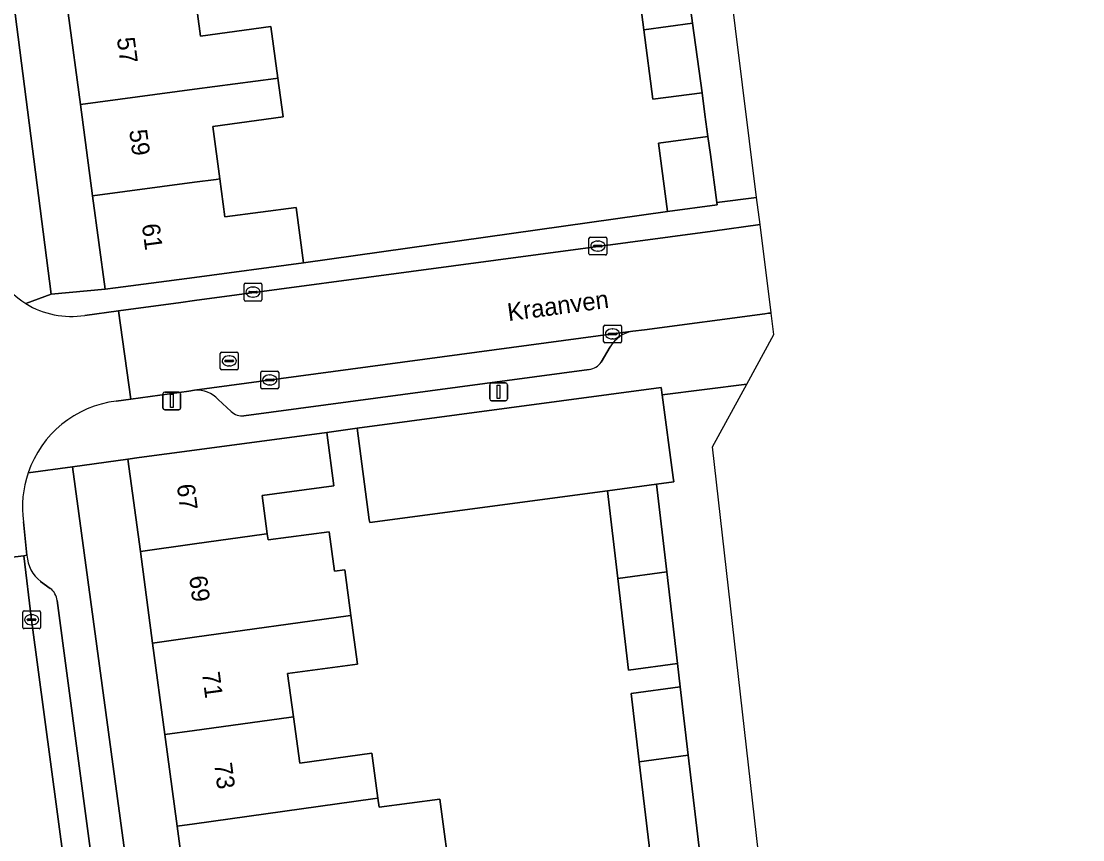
# Model space of a CAD drawing. Extents: x 163147 to 163550, y 380933 to 381639.
# Drawn here: x 163490.3 to 163549.9, y 381293.5 to 381339.4 of the extents above; entities that cross this region are included whole.
import ezdxf

# ---------------------------------------------------------------- set-up
doc = ezdxf.new("R2010")
doc.units = 0
for name, color, linetype in [('IMGEO_Erf', 7, 'Continuous'), ('IMGEO_Kolk', 7, 'Continuous'), ('IMGEO_Lichtmast', 7, 'Continuous'), ('IMGEO_Muur', 7, 'Continuous'), ('IMGEO_Openbare_ruimte_label', 7, 'Continuous'), ('IMGEO_Pand', 7, 'Continuous'), ('IMGEO_Pand_nummerreeks', 7, 'Continuous'), ('IMGEO_Parkeervlak_open', 7, 'Continuous'), ('IMGEO_Rijbaan_lokaal_open', 7, 'Continuous'), ('IMGEO_Rioolput', 7, 'Continuous'), ('IMGEO_Voetpad_open', 7, 'Continuous')]:
    doc.layers.add(name, color=color, linetype=linetype)

msp = doc.modelspace()

# ---------------------------------------------------------------- linework, layer by layer
at = {"layer": 'IMGEO_Erf'}
for points in [[(163487.783, 381356.32), (163491.94, 381324.111), (163494.978, 381324.392), (163494.274, 381329.637), (163493.586, 381334.763), (163492.898, 381339.89)], [(163500.033, 381340.835), (163500.331, 381338.604), (163504.288, 381339.132), (163504.676, 381336.232), (163504.966, 381334.06), (163501.026, 381333.533), (163501.42, 381330.584), (163501.705, 381328.452), (163505.703, 381328.986), (163506.119, 381325.868), (163526.558, 381328.752), (163526.055, 381332.589), (163528.823, 381332.956), (163528.656, 381334.194), (163528.491, 381335.418), (163525.733, 381335.053), (163525.222, 381338.955), (163524.714, 381342.835)], [(163525.611, 381292.402), (163524.968, 381297.87), (163524.517, 381301.709), (163527.27, 381302.09), (163527.116, 381303.397), (163524.363, 381303.016), (163523.757, 381308.165), (163523.178, 381313.092), (163509.829, 381311.3), (163509.807, 381311.462), (163509.122, 381316.592), (163507.426, 381316.365), (163507.826, 381313.367), (163503.792, 381312.828), (163504.081, 381310.668), (163504.126, 381310.33), (163507.551, 381310.789), (163507.848, 381308.578), (163508.435, 381308.656), (163508.778, 381306.087), (163509.142, 381303.362), (163505.221, 381302.826), (163505.549, 381300.408), (163505.901, 381297.81), (163509.948, 381298.359), (163510.29, 381295.834), (163510.358, 381295.333), (163513.772, 381295.791), (163514.431, 381290.881)]]:
    msp.add_lwpolyline(points, dxfattribs=at)
msp.add_lwpolyline([(163497.642, 381304.544), (163496.953, 381309.68), (163496.257, 381314.866), (163493.134, 381314.437), (163496.679, 381288.37), (163499.757, 381288.789), (163499.021, 381294.272), (163498.332, 381299.408)], close=True, dxfattribs=at)
at = {"layer": 'IMGEO_Kolk'}
for p, q in [((163522.141, 381326.39), (163522.141, 381327.242)), ((163522.216, 381327.316), (163523.068, 381327.316)), ((163523.142, 381327.242), (163523.142, 381326.39)), ((163522.4, 381326.81), (163522.4, 381326.822)), ((163522.838, 381326.773), (163522.44, 381326.773)), ((163522.443, 381326.859), (163522.841, 381326.859)), ((163522.629, 381327.096), (163522.654, 381327.096)), ((163522.884, 381326.822), (163522.884, 381326.81)), ((163523.068, 381326.316), (163522.216, 381326.316)), ((163522.652, 381326.536), (163522.627, 381326.536)), ((163502.776, 381323.807), (163502.776, 381324.659)), ((163502.851, 381324.733), (163503.703, 381324.733)), ((163503.035, 381324.227), (163503.035, 381324.239)), ((163503.473, 381324.19), (163503.075, 381324.19)), ((163503.078, 381324.276), (163503.476, 381324.276)), ((163503.264, 381324.513), (163503.289, 381324.513)), ((163503.519, 381324.239), (163503.519, 381324.227)), ((163503.777, 381324.659), (163503.777, 381323.807)), ((163503.703, 381323.733), (163502.851, 381323.733)), ((163503.287, 381323.953), (163503.262, 381323.953)), ((163522.964, 381321.459), (163522.964, 381322.311)), ((163523.039, 381322.385), (163523.891, 381322.385)), ((163523.223, 381321.879), (163523.223, 381321.891)), ((163523.661, 381321.842), (163523.263, 381321.842)), ((163523.266, 381321.928), (163523.664, 381321.928)), ((163523.452, 381322.165), (163523.477, 381322.165)), ((163523.707, 381321.891), (163523.707, 381321.879)), ((163523.965, 381322.311), (163523.965, 381321.459)), ((163523.891, 381321.385), (163523.039, 381321.385)), ((163523.475, 381321.605), (163523.45, 381321.605)), ((163503.72, 381318.877), (163503.72, 381319.729)), ((163503.795, 381319.803), (163504.647, 381319.803)), ((163504.208, 381319.583), (163504.233, 381319.583)), ((163504.721, 381319.729), (163504.721, 381318.877)), ((163503.979, 381319.297), (163503.979, 381319.309)), ((163504.417, 381319.26), (163504.019, 381319.26)), ((163504.022, 381319.346), (163504.42, 381319.346)), ((163504.231, 381319.023), (163504.206, 381319.023)), ((163504.463, 381319.309), (163504.463, 381319.297)), ((163504.647, 381318.803), (163503.795, 381318.803)), ((163490.421, 381306.349), (163491.273, 381306.349)), ((163490.346, 381305.423), (163490.346, 381306.275)), ((163490.605, 381305.843), (163490.605, 381305.855)), ((163491.043, 381305.806), (163490.645, 381305.806)), ((163490.648, 381305.892), (163491.046, 381305.892)), ((163490.834, 381306.129), (163490.859, 381306.129)), ((163491.089, 381305.855), (163491.089, 381305.843)), ((163491.347, 381306.275), (163491.347, 381305.423)), ((163491.273, 381305.349), (163490.421, 381305.349)), ((163490.857, 381305.569), (163490.832, 381305.569))]:
    msp.add_line(p, q, dxfattribs=at)
for points in [[(163522.141, 381326.39), (163522.141, 381327.242)], [(163522.216, 381327.316), (163523.068, 381327.316)], [(163523.142, 381327.242), (163523.142, 381326.39)], [(163523.068, 381326.316), (163522.216, 381326.316)], [(163502.776, 381323.807), (163502.776, 381324.659)], [(163502.851, 381324.733), (163503.703, 381324.733)], [(163503.777, 381324.659), (163503.777, 381323.807)], [(163503.703, 381323.733), (163502.851, 381323.733)], [(163522.964, 381321.459), (163522.964, 381322.311)], [(163523.039, 381322.385), (163523.891, 381322.385)], [(163523.965, 381322.311), (163523.965, 381321.459)], [(163523.891, 381321.385), (163523.039, 381321.385)], [(163503.72, 381318.877), (163503.72, 381319.729)], [(163503.795, 381319.803), (163504.647, 381319.803)], [(163504.721, 381319.729), (163504.721, 381318.877)], [(163504.647, 381318.803), (163503.795, 381318.803)], [(163490.421, 381306.349), (163491.273, 381306.349)], [(163490.346, 381305.423), (163490.346, 381306.275)], [(163491.347, 381306.275), (163491.347, 381305.423)], [(163491.273, 381305.349), (163490.421, 381305.349)]]:
    msp.add_lwpolyline(points, dxfattribs=at)
for centre, radius, start, end in [((163522.218, 381327.24), 0.0765, 91.55205, 178.44795), ((163522.218, 381327.24), 0.0765, 91.55205, 178.44795), ((163523.066, 381327.24), 0.0765, 1.55205, 88.44795), ((163523.066, 381327.24), 0.0765, 1.55205, 88.44795), ((163522.44, 381326.819), 0.0403, 85.87752, 175.75265), ((163522.437, 381326.809), 0.0366, 178.93798, 274.71019), ((163522.841, 381326.816), 0.043, 264.86636, 352.45326), ((163522.845, 381326.821), 0.0386, 1.73085, 96.63898), ((163522.218, 381326.392), 0.0765, 181.55205, 268.44795), ((163522.218, 381326.392), 0.0765, 181.55205, 268.44795), ((163523.066, 381326.392), 0.0765, 271.55205, 358.44795), ((163523.066, 381326.392), 0.0765, 271.55205, 358.44795), ((163502.853, 381324.657), 0.0765, 91.55205, 178.44795), ((163502.853, 381324.657), 0.0765, 91.55205, 178.44795), ((163503.075, 381324.236), 0.0403, 85.87752, 175.75265), ((163503.072, 381324.226), 0.0366, 178.93798, 274.71019), ((163503.476, 381324.233), 0.043, 264.86636, 352.45326), ((163503.48, 381324.238), 0.0386, 1.73085, 96.63898), ((163503.701, 381324.657), 0.0765, 1.55205, 88.44795), ((163503.701, 381324.657), 0.0765, 1.55205, 88.44795), ((163502.853, 381323.809), 0.0765, 181.55205, 268.44795), ((163502.853, 381323.809), 0.0765, 181.55205, 268.44795), ((163503.701, 381323.809), 0.0765, 271.55205, 358.44795), ((163503.701, 381323.809), 0.0765, 271.55205, 358.44795), ((163523.041, 381322.309), 0.0765, 91.55205, 178.44795), ((163523.041, 381322.309), 0.0765, 91.55205, 178.44795), ((163523.263, 381321.888), 0.0403, 85.87752, 175.75265), ((163523.26, 381321.878), 0.0366, 178.93798, 274.71019), ((163523.664, 381321.885), 0.043, 264.86636, 352.45326), ((163523.668, 381321.89), 0.0386, 1.73085, 96.63898), ((163523.889, 381322.309), 0.0765, 1.55205, 88.44795), ((163523.889, 381322.309), 0.0765, 1.55205, 88.44795), ((163523.041, 381321.461), 0.0765, 181.55205, 268.44795), ((163523.041, 381321.461), 0.0765, 181.55205, 268.44795), ((163523.889, 381321.461), 0.0765, 271.55205, 358.44795), ((163523.889, 381321.461), 0.0765, 271.55205, 358.44795), ((163503.797, 381319.727), 0.0765, 91.55205, 178.44795), ((163503.797, 381319.727), 0.0765, 91.55205, 178.44795), ((163504.645, 381319.727), 0.0765, 1.55205, 88.44795), ((163504.645, 381319.727), 0.0765, 1.55205, 88.44795), ((163503.797, 381318.879), 0.0765, 181.55205, 268.44795), ((163503.797, 381318.879), 0.0765, 181.55205, 268.44795), ((163504.019, 381319.306), 0.0403, 85.87752, 175.75265), ((163504.016, 381319.296), 0.0366, 178.93798, 274.71019), ((163504.42, 381319.303), 0.043, 264.86636, 352.45326), ((163504.424, 381319.308), 0.0386, 1.73085, 96.63898), ((163504.645, 381318.879), 0.0765, 271.55205, 358.44795), ((163504.645, 381318.879), 0.0765, 271.55205, 358.44795), ((163490.423, 381306.273), 0.0765, 91.55205, 178.44795), ((163490.423, 381306.273), 0.0765, 91.55205, 178.44795), ((163491.271, 381306.273), 0.0765, 1.55205, 88.44795), ((163491.271, 381306.273), 0.0765, 1.55205, 88.44795), ((163490.645, 381305.852), 0.0403, 85.87752, 175.75265), ((163490.642, 381305.842), 0.0366, 178.93798, 274.71019), ((163491.046, 381305.849), 0.043, 264.86636, 352.45326), ((163491.05, 381305.854), 0.0386, 1.73085, 96.63898), ((163490.423, 381305.425), 0.0765, 181.55205, 268.44795), ((163490.423, 381305.425), 0.0765, 181.55205, 268.44795), ((163491.271, 381305.425), 0.0765, 271.55205, 358.44795), ((163491.271, 381305.425), 0.0765, 271.55205, 358.44795)]:
    msp.add_arc(centre, radius, start, end, dxfattribs=at)
for centre, major_axis, ratio, start_param, end_param in [((163522.628, 381326.816), (-0.387, 0.002), 0.722429, 4.712389, 7.853982), ((163522.653, 381326.816), (-0.39, 0.002), 0.717154, 1.570796, 4.712389), ((163503.263, 381324.233), (-0.387, 0.002), 0.722429, 4.712389, 7.853982), ((163503.288, 381324.233), (-0.39, 0.002), 0.717154, 1.570796, 4.712389), ((163523.451, 381321.885), (-0.387, 0.002), 0.722429, 4.712389, 7.853982), ((163523.476, 381321.885), (-0.39, 0.002), 0.717154, 1.570796, 4.712389), ((163504.207, 381319.303), (-0.387, 0.002), 0.722429, 4.712389, 7.853982), ((163504.232, 381319.303), (-0.39, 0.002), 0.717154, 1.570796, 4.712389), ((163490.833, 381305.849), (-0.387, 0.002), 0.722429, 4.712389, 7.853982), ((163490.858, 381305.849), (-0.39, 0.002), 0.717154, 1.570796, 4.712389)]:
    msp.add_ellipse(centre, major_axis=major_axis, ratio=ratio, start_param=start_param, end_param=end_param, dxfattribs=at)
at = {"layer": 'IMGEO_Lichtmast'}
for p, q in [((163516.571, 381318.238), (163516.571, 381319.038)), ((163516.571, 381319.038), (163516.571, 381318.238)), ((163516.671, 381319.138), (163517.461, 381319.138)), ((163517.461, 381319.138), (163516.671, 381319.138)), ((163517.561, 381319.038), (163517.561, 381318.238)), ((163517.561, 381318.238), (163517.561, 381319.038)), ((163498.219, 381317.728), (163498.219, 381318.528)), ((163498.219, 381318.528), (163498.219, 381317.728)), ((163498.319, 381318.628), (163499.109, 381318.628)), ((163499.109, 381318.628), (163498.319, 381318.628)), ((163499.209, 381318.528), (163499.209, 381317.728)), ((163499.209, 381317.728), (163499.209, 381318.528)), ((163517.461, 381318.138), (163516.671, 381318.138)), ((163516.671, 381318.138), (163517.461, 381318.138)), ((163499.109, 381317.628), (163498.319, 381317.628)), ((163498.319, 381317.628), (163499.109, 381317.628))]:
    msp.add_line(p, q, dxfattribs=at)
for points in [[(163516.991, 381319.013), (163517.141, 381319.013), (163517.141, 381318.263), (163516.991, 381318.263), (163516.991, 381319.013)], [(163498.639, 381318.503), (163498.789, 381318.503), (163498.789, 381317.753), (163498.639, 381317.753), (163498.639, 381318.503)]]:
    msp.add_lwpolyline(points, dxfattribs=at)
for centre, start, end in [((163516.671, 381319.038), 90, 180), ((163516.671, 381319.038), 90, 180), ((163517.461, 381319.038), 0, 90), ((163517.461, 381319.038), 360, 90), ((163498.319, 381318.528), 90, 180), ((163498.319, 381318.528), 90, 180), ((163499.109, 381318.528), 0, 90), ((163499.109, 381318.528), 360, 90), ((163516.671, 381318.238), 180, 270), ((163516.671, 381318.238), 180, 270), ((163517.461, 381318.238), 270, 0), ((163517.461, 381318.238), 270, 0), ((163498.319, 381317.728), 180, 270), ((163498.319, 381317.728), 180, 270), ((163499.109, 381317.728), 270, 0), ((163499.109, 381317.728), 270, 0)]:
    msp.add_arc(centre, 0.1, start, end, dxfattribs=at)
at = {"layer": 'IMGEO_Muur'}
msp.add_lwpolyline([(163506.119, 381325.868), (163526.558, 381328.752)], dxfattribs=at)
at = {"layer": 'IMGEO_Pand'}
for points in [[(163527.441, 381343.197), (163524.714, 381342.835), (163525.222, 381338.955), (163527.965, 381339.319)], [(163504.676, 381336.232), (163504.288, 381339.132), (163500.331, 381338.604), (163500.033, 381340.835), (163499.837, 381340.809), (163492.898, 381339.89), (163493.586, 381334.763), (163500, 381335.613), (163504.561, 381336.217)], [(163527.965, 381339.319), (163525.222, 381338.955), (163525.733, 381335.053), (163528.491, 381335.418)], [(163501.42, 381330.584), (163501.026, 381333.533), (163504.966, 381334.06), (163504.676, 381336.232), (163504.561, 381336.217), (163500, 381335.613), (163493.586, 381334.763), (163494.274, 381329.637), (163500, 381330.396), (163501.218, 381330.557)], [(163528.823, 381332.956), (163526.055, 381332.589), (163526.558, 381328.752), (163529.342, 381329.128), (163529.325, 381329.257), (163528.958, 381331.96)], [(163501.42, 381330.584), (163501.218, 381330.557), (163500, 381330.396), (163494.274, 381329.637), (163494.978, 381324.392), (163495.551, 381324.468), (163500, 381325.057), (163506.119, 381325.868), (163505.703, 381328.986), (163501.705, 381328.452)], [(163525.933, 381313.462), (163526.899, 381313.591), (163526.867, 381313.827), (163526.248, 381318.462), (163526.192, 381318.885), (163509.122, 381316.592), (163509.807, 381311.462), (163509.829, 381311.3), (163523.178, 381313.092)], [(163504.081, 381310.668), (163503.792, 381312.828), (163507.826, 381313.367), (163507.426, 381316.365), (163500, 381315.368), (163496.878, 381314.949), (163496.257, 381314.866), (163496.953, 381309.68), (163500, 381310.102), (163503.902, 381310.643)], [(163526.511, 381308.547), (163525.933, 381313.462), (163523.178, 381313.092), (163523.757, 381308.165)], [(163508.435, 381308.656), (163507.848, 381308.578), (163507.551, 381310.789), (163504.126, 381310.33), (163504.081, 381310.668), (163503.902, 381310.643), (163500, 381310.102), (163496.953, 381309.68), (163497.642, 381304.544), (163500, 381304.87), (163508.624, 381306.066), (163508.778, 381306.087)], [(163527.116, 381303.397), (163526.511, 381308.547), (163523.757, 381308.165), (163524.363, 381303.016)], [(163508.778, 381306.087), (163508.624, 381306.066), (163500, 381304.87), (163497.642, 381304.544), (163498.332, 381299.408), (163500, 381299.639), (163505.296, 381300.373), (163505.549, 381300.408), (163505.221, 381302.826), (163509.142, 381303.362)], [(163527.27, 381302.09), (163524.517, 381301.709), (163524.968, 381297.87), (163527.721, 381298.252)], [(163499.021, 381294.272), (163500, 381294.407), (163510.008, 381295.795), (163510.29, 381295.834), (163509.948, 381298.359), (163505.901, 381297.81), (163505.549, 381300.408), (163505.296, 381300.373), (163500, 381299.639), (163498.332, 381299.408)], [(163524.968, 381297.87), (163525.611, 381292.402), (163528.371, 381292.726), (163527.721, 381298.252)], [(163513.772, 381295.791), (163510.358, 381295.333), (163510.29, 381295.834), (163510.008, 381295.795), (163500, 381294.407), (163499.021, 381294.272), (163499.757, 381288.789), (163500, 381288.822), (163504.721, 381289.462), (163506.927, 381289.76), (163506.951, 381289.586), (163511.289, 381290.168), (163511.262, 381290.373), (163511.251, 381290.454), (163514.431, 381290.881)]]:
    msp.add_lwpolyline(points, close=True, dxfattribs=at)
at = {"layer": 'IMGEO_Parkeervlak_open'}
for points in [[(163532.367, 381323.051), (163532.365, 381323.067), (163532.223, 381323.048), (163532.367, 381323.051)], [(163524.612, 381322.04), (163500, 381318.735)], [(163522.828, 381320.305), (163523.34, 381321.154)], [(163502.768, 381317.294), (163522.155, 381319.882)], [(163501.319, 381318.211), (163502.055, 381317.543)], [(163490.584, 381309.465), (163490.402, 381309.443), (163490.846, 381305.849), (163493.759, 381284.035), (163496.541, 381263.222), (163497.43, 381256.373), (163497.739, 381256.415), (163498.362, 381251.625), (163498.069, 381251.55), (163498.277, 381250), (163499.186, 381243.223), (163500, 381237.114), (163502.031, 381221.873), (163503.782, 381208.782)], [(163491.895, 381307.604), (163491.355, 381308.001)], [(163504.96, 381211.766), (163500, 381248.982), (163499.864, 381250), (163492.278, 381306.923)]]:
    msp.add_lwpolyline(points, dxfattribs=at)
for centre, radius, start, end in [((163532.34, 381321.083), 1.968, 89.20328, 89.21682), ((163524.884, 381320.293), 1.768, 98.86148, 150.85609), ((163521.96, 381320.939), 1.075, 280.45491, 323.84619), ((163500.105, 381317.077), 1.662, 43.05366, 93.6134), ((163502.673, 381318.166), 0.878, 225.26376, 276.23492), ((163492.583, 381309.583), 2.002, 183.36688, 232.17923), ((163491.313, 381306.828), 0.97, 5.59617, 53.11135)]:
    msp.add_arc(centre, radius, start, end, dxfattribs=at)
at = {"layer": 'IMGEO_Rijbaan_lokaal_open'}
for points in [[(163527.441, 381343.197), (163527.965, 381339.319), (163528.491, 381335.418), (163528.656, 381334.194), (163528.823, 381332.956), (163528.958, 381331.96), (163529.325, 381329.257), (163531.559, 381329.55), (163510.586, 381498.135)], [(163532.365, 381323.067), (163531.749, 381328.021), (163531.749, 381328.021), (163529.073, 381327.662), (163500, 381323.758), (163499.23, 381323.655), (163495.731, 381323.177), (163496.421, 381318.221), (163499.683, 381318.682), (163500, 381318.735), (163524.612, 381322.04), (163525.264, 381322.126), (163532.015, 381323.02), (163532.223, 381323.048), (163532.365, 381323.067)], [(163495.731, 381323.177), (163493.833, 381322.927)], [(163495.598, 381318.116), (163496.421, 381318.221), (163495.731, 381323.177)], [(163549.87, 381132.002), (163529.08, 381315.546), (163531.005, 381319.076), (163526.248, 381318.462), (163526.867, 381313.827), (163526.899, 381313.591), (163525.933, 381313.462), (163526.511, 381308.547), (163527.116, 381303.397), (163527.27, 381302.09), (163527.721, 381298.252), (163528.371, 381292.726)], [(163486.239, 381310.132), (163486.415, 381308.977), (163486.73, 381309.012), (163490.402, 381309.443), (163490.584, 381309.465), (163490.394, 381311.344)]]:
    msp.add_lwpolyline(points, dxfattribs=at)
msp.add_lwpolyline([(163494.08, 381255.92), (163497.43, 381256.373), (163496.541, 381263.222), (163493.759, 381284.035), (163490.846, 381305.849), (163490.402, 381309.443), (163486.73, 381309.012), (163487.468, 381304.821), (163488.958, 381294.533), (163488.987, 381294.337), (163489.02, 381294.106), (163490.135, 381285.185), (163490.149, 381285.047), (163490.358, 381282.994), (163493.013, 381263.045)], close=True, dxfattribs=at)
for centre, radius, start, end in [((163493.064, 381327.696), 4.828, 185.34699, 238.2884), ((163493.068, 381327.697), 4.831, 238.24928, 279.11087), ((163496.315, 381312.18), 5.979, 96.88985, 161.2586), ((163496.325, 381312.178), 5.989, 161.26652, 187.99994)]:
    msp.add_arc(centre, radius, start, end, dxfattribs=at)
at = {"layer": 'IMGEO_Rioolput'}
for p, q in [((163501.443, 381319.944), (163501.443, 381320.796)), ((163501.518, 381320.87), (163502.37, 381320.87)), ((163501.931, 381320.65), (163501.956, 381320.65)), ((163502.444, 381320.796), (163502.444, 381319.944)), ((163501.702, 381320.364), (163501.702, 381320.376)), ((163502.14, 381320.327), (163501.742, 381320.327)), ((163501.745, 381320.413), (163502.143, 381320.413)), ((163501.954, 381320.09), (163501.929, 381320.09)), ((163502.186, 381320.376), (163502.186, 381320.364)), ((163502.37, 381319.87), (163501.518, 381319.87))]:
    msp.add_line(p, q, dxfattribs=at)
for points in [[(163501.443, 381319.944), (163501.443, 381320.796)], [(163501.518, 381320.87), (163502.37, 381320.87)], [(163502.444, 381320.796), (163502.444, 381319.944)], [(163502.37, 381319.87), (163501.518, 381319.87)]]:
    msp.add_lwpolyline(points, dxfattribs=at)
for centre, radius, start, end in [((163501.52, 381320.794), 0.0765, 91.55205, 178.44795), ((163501.52, 381320.794), 0.0765, 91.55205, 178.44795), ((163502.368, 381320.794), 0.0765, 1.55205, 88.44795), ((163502.368, 381320.794), 0.0765, 1.55205, 88.44795), ((163501.742, 381320.373), 0.0403, 85.87752, 175.75265), ((163501.739, 381320.363), 0.0366, 178.93798, 274.71019), ((163502.143, 381320.37), 0.043, 264.86636, 352.45326), ((163502.147, 381320.375), 0.0386, 1.73085, 96.63898), ((163501.52, 381319.946), 0.0765, 181.55205, 268.44795), ((163501.52, 381319.946), 0.0765, 181.55205, 268.44795), ((163502.368, 381319.946), 0.0765, 271.55205, 358.44795), ((163502.368, 381319.946), 0.0765, 271.55205, 358.44795)]:
    msp.add_arc(centre, radius, start, end, dxfattribs=at)
for centre, major_axis, ratio, start_param, end_param in [((163501.93, 381320.37), (-0.387, 0.002), 0.722429, 4.712389, 7.853982), ((163501.955, 381320.37), (-0.39, 0.002), 0.717154, 1.570796, 4.712389)]:
    msp.add_ellipse(centre, major_axis=major_axis, ratio=ratio, start_param=start_param, end_param=end_param, dxfattribs=at)
at = {"layer": 'IMGEO_Voetpad_open'}
for points in [[(163490.526, 381323.589), (163491.94, 381324.111), (163487.783, 381356.32), (163487.612, 381356.297), (163487.586, 381356.488), (163486.908, 381361.54), (163486.877, 381361.772), (163487.388, 381361.841), (163486.74, 381366.662), (163486.09, 381371.504), (163485.566, 381371.433), (163485.538, 381371.644), (163484.859, 381376.696), (163484.837, 381376.861), (163474.607, 381453.41)], [(163531.559, 381329.55), (163529.325, 381329.257), (163529.342, 381329.128), (163526.558, 381328.752), (163506.119, 381325.868), (163500, 381325.057), (163495.551, 381324.468), (163494.978, 381324.392), (163491.94, 381324.111), (163490.526, 381323.589)], [(163493.833, 381322.927), (163495.731, 381323.177), (163499.23, 381323.655), (163500, 381323.758), (163529.073, 381327.662), (163531.749, 381328.021), (163531.749, 381328.021), (163531.559, 381329.55)], [(163532.367, 381323.051), (163532.223, 381323.048), (163532.015, 381323.02), (163525.264, 381322.126), (163524.612, 381322.04)], [(163531.005, 381319.076), (163532.517, 381321.849), (163532.367, 381323.051)], [(163523.34, 381321.154), (163522.828, 381320.305)], [(163522.155, 381319.882), (163502.768, 381317.294)], [(163490.653, 381314.101), (163493.134, 381314.437), (163496.257, 381314.866), (163496.878, 381314.949), (163500, 381315.368), (163507.426, 381316.365), (163509.122, 381316.592), (163526.192, 381318.885), (163526.248, 381318.462), (163531.005, 381319.076)], [(163500, 381318.735), (163499.683, 381318.682), (163496.421, 381318.221), (163495.598, 381318.116)], [(163502.055, 381317.543), (163501.319, 381318.211)], [(163496.679, 381288.37), (163493.134, 381314.437), (163490.653, 381314.101)], [(163490.394, 381311.344), (163490.584, 381309.465)], [(163491.355, 381308.001), (163491.895, 381307.604)], [(163492.278, 381306.923), (163499.864, 381250), (163500, 381248.982), (163504.96, 381211.766)]]:
    msp.add_lwpolyline(points, dxfattribs=at)
for centre, radius, start, end in [((163493.064, 381327.696), 4.828, 185.34699, 238.2884), ((163493.068, 381327.697), 4.831, 238.24928, 279.11087), ((163532.34, 381321.083), 1.968, 89.20328, 89.21682), ((163524.884, 381320.293), 1.768, 98.86148, 150.85609), ((163521.96, 381320.939), 1.075, 280.45491, 323.84619), ((163500.105, 381317.077), 1.662, 43.05366, 93.6134), ((163496.315, 381312.18), 5.979, 96.88985, 161.2586), ((163502.673, 381318.166), 0.878, 225.26376, 276.23492), ((163496.325, 381312.178), 5.989, 161.26652, 187.99994), ((163492.583, 381309.583), 2.002, 183.36688, 232.17923), ((163491.313, 381306.828), 0.97, 5.59617, 53.11135)]:
    msp.add_arc(centre, radius, start, end, dxfattribs=at)

# ---------------------------------------------------------------- texts
at = {"layer": 'IMGEO_Openbare_ruimte_label'}
msp.add_text('Kraanven', height=1, rotation=7.58707, dxfattribs=at).set_placement((163517.628, 381322.603))
at = {"layer": 'IMGEO_Pand_nummerreeks'}
for s, rotation, p in [('57', 277.64296, (163495.63, 381338.479)), ('59', 277.64296, (163496.324, 381333.305)), ('61', 277.64296, (163497.033, 381328.02)), ('67', 277.64443, (163498.994, 381313.412)), ('69', 277.64305, (163499.687, 381308.267)), ('71', 277.64443, (163500.409, 381302.869)), ('73', 277.64443, (163501.094, 381297.766))]:
    msp.add_text(s, height=1, rotation=rotation, dxfattribs=at).set_placement(p)

doc.saveas('drawing.dxf')
